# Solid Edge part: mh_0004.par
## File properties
Title: holder joint
Author: edge
Template: normal.par
Last saved by: edge
Revision: 37
Application: Solid Edge
Material: エストラマ
非切断部品: False
文書内容のタイプ: 0
Density: 0.001030 g/mm^3
Accuracy: 0.99
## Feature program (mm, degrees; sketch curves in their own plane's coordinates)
sketch for "unnamed Protrusion 1" plane through (0, 0, 0) normal (0, -1, 0) x-axis (1, 0, 0)
extrude "unnamed Protrusion 1" add finite 380 along -normal
thinwall "Thinwall_1"  Thickness = 1 mm
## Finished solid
Body 1: solid body, 10 faces, 24 edges, 16 vertices.
  Faces by surface: plane 10
  Edges by curve: line 24
Bounding box of the edges (mm): 40.000 x 380.000 x 15.000, from (-20, 0, -7.5) to (20, 380, 7.5).
Planar faces by outward normal: +x 2, +y 1, +z 2, -x 2, -y 1, -z 2
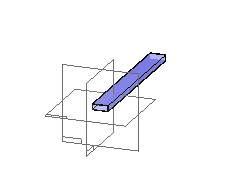
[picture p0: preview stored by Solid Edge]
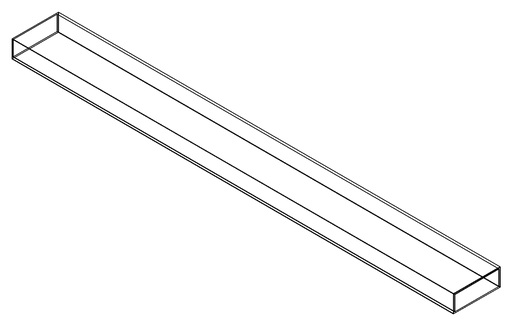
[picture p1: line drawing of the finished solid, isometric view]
